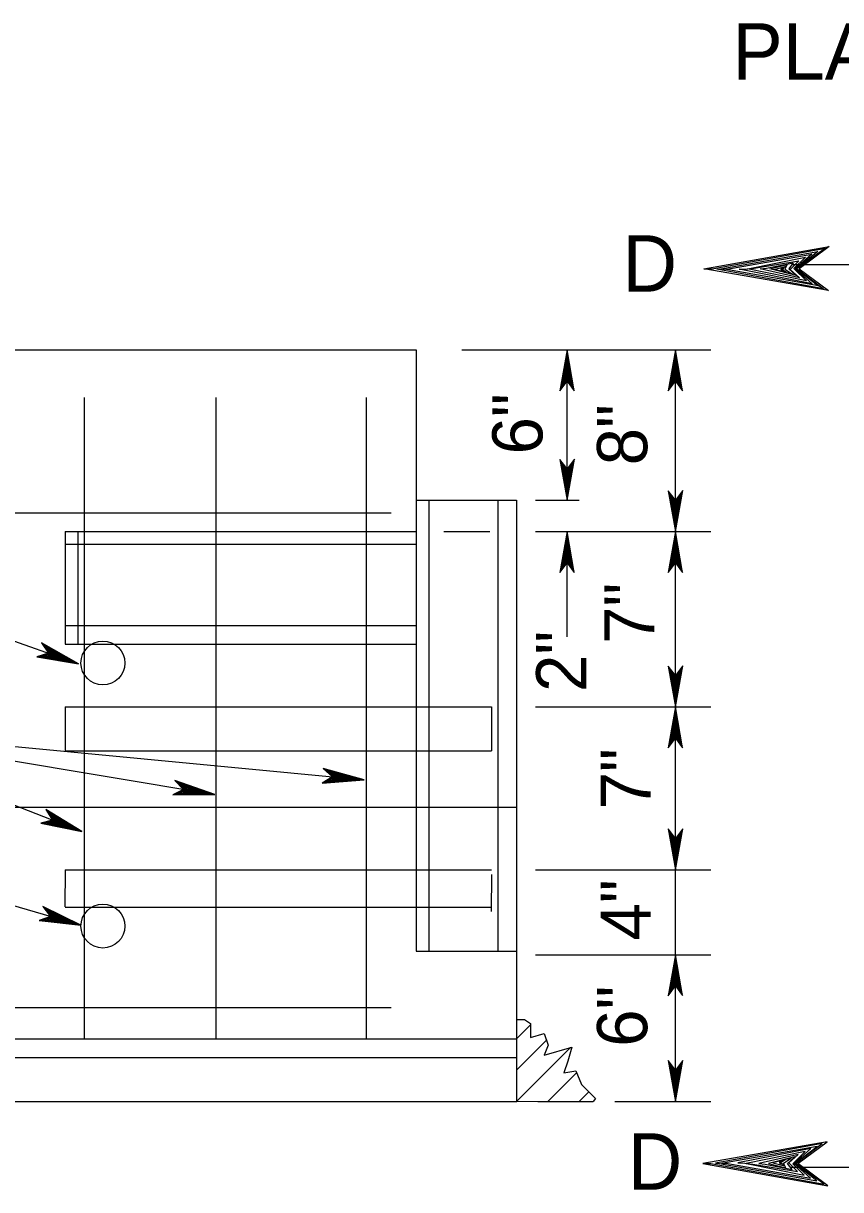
# Model space of a CAD drawing. Extents: x 499883 to 500983, y 499104 to 499764.
# Drawn here: x 500056.1 to 500121.3, y 499574.2 to 499667.2 of the extents above; entities that cross this region are included whole.
import ezdxf

# ---------------------------------------------------------------- set-up
doc = ezdxf.new("R2010")
doc.units = 0
for name, color, linetype in [('24', 7, 'Continuous'), ('5', 7, 'Continuous'), ('60', 7, 'Continuous')]:
    doc.layers.add(name, color=color, linetype=linetype)

msp = doc.modelspace()

# ---------------------------------------------------------------- linework, layer by layer
at = {"layer": '24'}
for points in [[(500099.463, 499641.156), (500098.884, 499637.882), (500099.463, 499638.665), (500100.033, 499637.899), (500099.463, 499641.156), (500099.469, 499640.939), (500098.927, 499637.974), (500099.47, 499638.726), (500099.988, 499638.032), (500099.479, 499640.822), (500099.463, 499640.713), (500099.011, 499638.173), (500099.47, 499638.743), (500099.914, 499638.157), (500099.462, 499640.663), (500099.479, 499640.554), (500099.078, 499638.334), (500099.462, 499638.766), (500099.862, 499638.325), (500099.479, 499640.238), (500099.479, 499640.053), (500099.161, 499638.499), (500099.454, 499638.801), (500099.779, 499638.475), (500099.463, 499640.02), (500099.453, 499639.845), (500099.253, 499638.677), (500099.479, 499638.901), (500099.704, 499638.658), (500099.463, 499639.685), (500099.446, 499639.52), (500099.312, 499638.818), (500099.47, 499638.934), (500099.645, 499638.742), (500099.462, 499639.435), (500099.354, 499638.977), (500099.479, 499639.043), (500099.605, 499638.842), (500099.479, 499639.319), (500099.404, 499639.019), (500099.503, 499639.145), (500099.562, 499639), (500099.47, 499639.144), (500099.454, 499639.069)], [(500108.099, 499641.156), (500107.52, 499637.882), (500108.099, 499638.665), (500108.669, 499637.899), (500108.099, 499641.156), (500108.105, 499640.939), (500107.563, 499637.974), (500108.106, 499638.726), (500108.624, 499638.032), (500108.115, 499640.822), (500108.099, 499640.713), (500107.647, 499638.173), (500108.106, 499638.743), (500108.55, 499638.157), (500108.099, 499640.663), (500108.115, 499640.554), (500107.714, 499638.334), (500108.099, 499638.766), (500108.498, 499638.325), (500108.116, 499640.238), (500108.115, 499640.053), (500107.797, 499638.499), (500108.09, 499638.801), (500108.415, 499638.475), (500108.099, 499640.02), (500108.089, 499639.845), (500107.889, 499638.677), (500108.116, 499638.901), (500108.34, 499638.658), (500108.099, 499639.685), (500108.082, 499639.52), (500107.948, 499638.818), (500108.106, 499638.934), (500108.281, 499638.742), (500108.099, 499639.435), (500107.99, 499638.977), (500108.115, 499639.043), (500108.241, 499638.842), (500108.116, 499639.319), (500108.04, 499639.019), (500108.139, 499639.145), (500108.198, 499639), (500108.106, 499639.144), (500108.09, 499639.069)], [(500099.463, 499629.166), (500100.042, 499632.44), (500099.463, 499631.658), (500098.893, 499632.423), (500099.463, 499629.166), (500099.457, 499629.383), (500099.999, 499632.348), (500099.456, 499631.597), (500098.938, 499632.291), (500099.447, 499629.5), (500099.463, 499629.61), (500099.914, 499632.149), (500099.456, 499631.58), (500099.012, 499632.166), (500099.463, 499629.66), (500099.447, 499629.768), (500099.848, 499631.988), (500099.463, 499631.557), (500099.064, 499631.998), (500099.446, 499630.084), (500099.447, 499630.269), (500099.765, 499631.824), (500099.472, 499631.521), (500099.147, 499631.847), (500099.463, 499630.302), (500099.473, 499630.477), (500099.673, 499631.646), (500099.446, 499631.421), (500099.222, 499631.665), (500099.463, 499630.638), (500099.479, 499630.803), (500099.614, 499631.504), (500099.456, 499631.389), (500099.281, 499631.58), (500099.463, 499630.888), (500099.572, 499631.346), (500099.447, 499631.28), (500099.321, 499631.48), (500099.446, 499631.003), (500099.521, 499631.304), (500099.423, 499631.178), (500099.364, 499631.322), (500099.456, 499631.179), (500099.472, 499631.254)], [(500108.099, 499626.667), (500108.678, 499629.941), (500108.099, 499629.159), (500107.529, 499629.925), (500108.099, 499626.667), (500108.093, 499626.885), (500108.635, 499629.85), (500108.092, 499629.098), (500107.574, 499629.792), (500108.083, 499627.002), (500108.099, 499627.111), (500108.551, 499629.651), (500108.092, 499629.081), (500107.648, 499629.667), (500108.099, 499627.161), (500108.083, 499627.27), (500108.484, 499629.49), (500108.099, 499629.058), (500107.7, 499629.499), (500108.082, 499627.586), (500108.083, 499627.771), (500108.401, 499629.325), (500108.109, 499629.023), (500107.783, 499629.349), (500108.099, 499627.804), (500108.109, 499627.979), (500108.309, 499629.147), (500108.082, 499628.923), (500107.859, 499629.166), (500108.099, 499628.139), (500108.116, 499628.304), (500108.25, 499629.006), (500108.092, 499628.89), (500107.917, 499629.082), (500108.099, 499628.39), (500108.208, 499628.847), (500108.083, 499628.781), (500107.957, 499628.982), (500108.082, 499628.505), (500108.158, 499628.805), (500108.059, 499628.679), (500108, 499628.824), (500108.092, 499628.68), (500108.109, 499628.755)], [(500099.463, 499626.667), (500098.884, 499623.394), (500099.463, 499624.176), (500100.033, 499623.41), (500099.463, 499626.667), (500099.469, 499626.45), (500098.927, 499623.485), (500099.47, 499624.237), (500099.988, 499623.543), (500099.479, 499626.333), (500099.463, 499626.224), (500099.011, 499623.684), (500099.47, 499624.254), (500099.914, 499623.668), (500099.462, 499626.174), (500099.479, 499626.065), (500099.078, 499623.845), (500099.462, 499624.277), (500099.862, 499623.836), (500099.479, 499625.749), (500099.479, 499625.564), (500099.161, 499624.01), (500099.454, 499624.312), (500099.779, 499623.986), (500099.463, 499625.531), (500099.453, 499625.356), (500099.253, 499624.188), (500099.479, 499624.412), (500099.704, 499624.169), (500099.463, 499625.196), (500099.446, 499625.031), (500099.312, 499624.329), (500099.47, 499624.445), (500099.645, 499624.253), (500099.462, 499624.945), (500099.354, 499624.488), (500099.479, 499624.554), (500099.605, 499624.353), (500099.479, 499624.83), (500099.404, 499624.53), (500099.503, 499624.656), (500099.562, 499624.511), (500099.47, 499624.655), (500099.454, 499624.58)], [(500108.099, 499626.667), (500107.52, 499623.394), (500108.099, 499624.176), (500108.669, 499623.41), (500108.099, 499626.667), (500108.105, 499626.45), (500107.563, 499623.485), (500108.106, 499624.237), (500108.624, 499623.543), (500108.115, 499626.333), (500108.099, 499626.224), (500107.647, 499623.684), (500108.106, 499624.254), (500108.55, 499623.668), (500108.099, 499626.174), (500108.115, 499626.065), (500107.714, 499623.845), (500108.099, 499624.277), (500108.498, 499623.836), (500108.116, 499625.749), (500108.115, 499625.564), (500107.797, 499624.01), (500108.09, 499624.312), (500108.415, 499623.986), (500108.099, 499625.531), (500108.089, 499625.356), (500107.889, 499624.188), (500108.116, 499624.412), (500108.34, 499624.169), (500108.099, 499625.196), (500108.082, 499625.031), (500107.948, 499624.329), (500108.106, 499624.445), (500108.281, 499624.253), (500108.099, 499624.945), (500107.99, 499624.488), (500108.115, 499624.554), (500108.241, 499624.353), (500108.116, 499624.83), (500108.04, 499624.53), (500108.139, 499624.656), (500108.198, 499624.511), (500108.106, 499624.655), (500108.09, 499624.58)], [(500108.099, 499612.678), (500108.678, 499615.952), (500108.099, 499615.17), (500107.529, 499615.935), (500108.099, 499612.678), (500108.093, 499612.896), (500108.635, 499615.86), (500108.092, 499615.109), (500107.574, 499615.803), (500108.083, 499613.013), (500108.099, 499613.122), (500108.551, 499615.662), (500108.092, 499615.092), (500107.648, 499615.678), (500108.099, 499613.172), (500108.083, 499613.28), (500108.484, 499615.5), (500108.099, 499615.069), (500107.7, 499615.51), (500108.082, 499613.597), (500108.083, 499613.781), (500108.401, 499615.336), (500108.109, 499615.034), (500107.783, 499615.359), (500108.099, 499613.814), (500108.109, 499613.989), (500108.309, 499615.158), (500108.082, 499614.933), (500107.859, 499615.177), (500108.099, 499614.15), (500108.116, 499614.315), (500108.25, 499615.017), (500108.092, 499614.901), (500107.917, 499615.092), (500108.099, 499614.4), (500108.208, 499614.858), (500108.083, 499614.792), (500107.957, 499614.993), (500108.082, 499614.516), (500108.158, 499614.816), (500108.059, 499614.69), (500108, 499614.834), (500108.092, 499614.691), (500108.109, 499614.766)], [(500108.099, 499612.678), (500107.52, 499609.404), (500108.099, 499610.187), (500108.669, 499609.421), (500108.099, 499612.678), (500108.105, 499612.461), (500107.563, 499609.496), (500108.106, 499610.248), (500108.624, 499609.553), (500108.115, 499612.343), (500108.099, 499612.234), (500107.647, 499609.695), (500108.106, 499610.264), (500108.55, 499609.679), (500108.099, 499612.185), (500108.115, 499612.076), (500107.714, 499609.856), (500108.099, 499610.288), (500108.498, 499609.847), (500108.116, 499611.76), (500108.115, 499611.575), (500107.797, 499610.02), (500108.09, 499610.323), (500108.415, 499609.997), (500108.099, 499611.542), (500108.089, 499611.367), (500107.889, 499610.198), (500108.116, 499610.423), (500108.34, 499610.179), (500108.099, 499611.207), (500108.082, 499611.042), (500107.948, 499610.339), (500108.106, 499610.455), (500108.281, 499610.264), (500108.099, 499610.956), (500107.99, 499610.498), (500108.115, 499610.564), (500108.241, 499610.364), (500108.116, 499610.841), (500108.04, 499610.54), (500108.139, 499610.666), (500108.198, 499610.522), (500108.106, 499610.666), (500108.09, 499610.59)], [(500108.099, 499599.688), (500108.678, 499602.962), (500108.099, 499602.18), (500107.529, 499602.945), (500108.099, 499599.688), (500108.093, 499599.906), (500108.635, 499602.871), (500108.092, 499602.119), (500107.574, 499602.813), (500108.083, 499600.023), (500108.099, 499600.132), (500108.551, 499602.672), (500108.092, 499602.102), (500107.648, 499602.688), (500108.099, 499600.182), (500108.083, 499600.291), (500108.484, 499602.511), (500108.099, 499602.079), (500107.7, 499602.52), (500108.082, 499600.607), (500108.083, 499600.792), (500108.401, 499602.346), (500108.109, 499602.044), (500107.783, 499602.37), (500108.099, 499600.825), (500108.109, 499601), (500108.309, 499602.168), (500108.082, 499601.943), (500107.859, 499602.187), (500108.099, 499601.16), (500108.116, 499601.325), (500108.25, 499602.027), (500108.092, 499601.911), (500107.917, 499602.103), (500108.099, 499601.41), (500108.208, 499601.868), (500108.083, 499601.802), (500107.957, 499602.003), (500108.082, 499601.526), (500108.158, 499601.826), (500108.059, 499601.7), (500108, 499601.845), (500108.092, 499601.701), (500108.109, 499601.776)], [(500108.099, 499592.909), (500107.52, 499589.635), (500108.099, 499590.417), (500108.669, 499589.652), (500108.099, 499592.909), (500108.105, 499592.691), (500107.563, 499589.727), (500108.106, 499590.478), (500108.624, 499589.784), (500108.115, 499592.574), (500108.099, 499592.465), (500107.647, 499589.925), (500108.106, 499590.495), (500108.55, 499589.909), (500108.099, 499592.415), (500108.115, 499592.307), (500107.714, 499590.086), (500108.099, 499590.518), (500108.498, 499590.077), (500108.116, 499591.99), (500108.115, 499591.806), (500107.797, 499590.251), (500108.09, 499590.553), (500108.415, 499590.228), (500108.099, 499591.772), (500108.089, 499591.598), (500107.889, 499590.429), (500108.116, 499590.654), (500108.34, 499590.41), (500108.099, 499591.437), (500108.082, 499591.272), (500107.948, 499590.57), (500108.106, 499590.686), (500108.281, 499590.495), (500108.099, 499591.187), (500107.99, 499590.729), (500108.115, 499590.795), (500108.241, 499590.594), (500108.116, 499591.071), (500108.04, 499590.771), (500108.139, 499590.897), (500108.198, 499590.752), (500108.106, 499590.896), (500108.09, 499590.821)], [(500108.099, 499581.202), (500108.678, 499584.476), (500108.099, 499583.694), (500107.529, 499584.459), (500108.099, 499581.202), (500108.093, 499581.419), (500108.635, 499584.384), (500108.092, 499583.633), (500107.574, 499584.327), (500108.083, 499581.537), (500108.099, 499581.646), (500108.551, 499584.186), (500108.092, 499583.616), (500107.648, 499584.202), (500108.099, 499581.696), (500108.083, 499581.805), (500108.484, 499584.024), (500108.099, 499583.593), (500107.7, 499584.034), (500108.082, 499582.121), (500108.083, 499582.305), (500108.401, 499583.86), (500108.109, 499583.558), (500107.783, 499583.883), (500108.099, 499582.338), (500108.109, 499582.513), (500108.309, 499583.682), (500108.082, 499583.457), (500107.859, 499583.701), (500108.099, 499582.674), (500108.116, 499582.839), (500108.25, 499583.541), (500108.092, 499583.425), (500107.917, 499583.616), (500108.099, 499582.924), (500108.208, 499583.382), (500108.083, 499583.316), (500107.957, 499583.517), (500108.082, 499583.04), (500108.158, 499583.34), (500108.059, 499583.214), (500108, 499583.358), (500108.092, 499583.215), (500108.109, 499583.29)]]:
    msp.add_lwpolyline(points, dxfattribs=at)
at = {"layer": '5'}
for p, q in [((500127.405, 499647.934), (500117.412, 499647.934)), ((500014.216, 499641.156), (500087.439, 499641.156)), ((500087.439, 499641.156), (500087.439, 499629.166)), ((500091.082, 499641.156), (500110.933, 499641.156)), ((500099.463, 499629.166), (500099.463, 499641.156)), ((500108.099, 499626.667), (500108.099, 499641.156)), ((500060.959, 499637.369), (500060.959, 499586.199)), ((500071.451, 499637.369), (500071.451, 499586.199)), ((500083.442, 499637.369), (500083.442, 499586.199)), ((500087.439, 499629.166), (500095.433, 499629.166)), ((500087.439, 499629.166), (500087.439, 499593.193)), ((500088.438, 499629.166), (500088.438, 499593.193)), ((500093.934, 499629.166), (500093.934, 499593.193)), ((500095.433, 499629.166), (500095.433, 499581.202)), ((500096.945, 499629.166), (500100.429, 499629.166)), ((500014.216, 499628.167), (500085.44, 499628.167)), ((500059.46, 499626.667), (500087.439, 499626.667)), ((500059.46, 499626.667), (500059.46, 499617.675)), ((500060.459, 499626.667), (500060.459, 499617.675)), ((500089.64, 499626.667), (500093.292, 499626.667)), ((500096.945, 499626.667), (500110.933, 499626.667)), ((500099.463, 499618.265), (500099.463, 499626.667)), ((500108.099, 499612.678), (500108.099, 499626.667)), ((500059.46, 499625.668), (500087.439, 499625.668)), ((500046.578, 499621.022), (500060.517, 499616.121)), ((500059.46, 499619.173), (500087.439, 499619.173)), ((500059.46, 499617.675), (500087.439, 499617.675)), ((500059.46, 499612.678), (500093.434, 499612.678)), ((500059.46, 499612.678), (500059.46, 499609.181)), ((500093.434, 499612.678), (500093.434, 499609.181)), ((500096.945, 499612.678), (500110.933, 499612.678)), ((500108.099, 499599.688), (500108.099, 499612.678)), ((500039.465, 499611.026), (500083.279, 499606.856)), ((500039.465, 499611.026), (500071.389, 499605.679)), ((500039.465, 499611.026), (500060.794, 499602.736)), ((500059.46, 499609.181), (500093.434, 499609.181)), ((500014.216, 499604.685), (500095.433, 499604.685)), ((500039.85, 499601.319), (500060.709, 499595.264)), ((500059.46, 499599.688), (500059.428, 499596.737)), ((500059.46, 499599.688), (500093.434, 499599.688)), ((500096.945, 499599.688), (500110.933, 499599.688)), ((500108.099, 499592.909), (500108.099, 499599.688)), ((500093.43, 499599.315), (500093.398, 499596.364)), ((500059.46, 499596.69), (500093.434, 499596.69)), ((500087.439, 499593.193), (500095.433, 499593.193)), ((500096.945, 499592.909), (500110.933, 499592.909)), ((500108.099, 499581.202), (500108.099, 499592.909)), ((500014.216, 499588.697), (500085.44, 499588.697)), ((500095.433, 499586.199), (500096.539, 499587.305)), ((500014.216, 499586.199), (500095.433, 499586.199)), ((500095.433, 499583.7), (500097.82, 499586.087)), ((500014.216, 499584.699), (500095.433, 499584.699)), ((500095.433, 499581.202), (500099.731, 499585.5)), ((500097.931, 499581.202), (500100.219, 499583.49)), ((500100.429, 499581.202), (500101.198, 499581.971)), ((500014.216, 499581.202), (500095.433, 499581.202)), ((500097.137, 499581.202), (500101.537, 499581.202)), ((500103.262, 499581.202), (500110.933, 499581.202)), ((500127.305, 499575.943), (500117.312, 499575.943))]:
    msp.add_line(p, q, dxfattribs=at)
for points in [[(500110.372, 499647.632), (500120.344, 499649.395), (500117.962, 499647.632), (500120.292, 499645.897), (500110.372, 499647.632), (500111.035, 499647.614), (500120.064, 499649.264), (500117.775, 499647.61), (500119.89, 499646.034), (500111.392, 499647.583), (500111.724, 499647.632), (500119.459, 499649.007), (500117.724, 499647.612), (500119.509, 499646.258), (500111.876, 499647.632), (500112.207, 499647.583), (500118.969, 499648.803), (500117.654, 499647.632), (500118.996, 499646.416), (500113.17, 499647.582), (500113.733, 499647.583), (500118.467, 499648.552), (500117.546, 499647.66), (500118.538, 499646.669), (500113.833, 499647.632), (500114.366, 499647.663), (500117.926, 499648.272), (500117.241, 499647.581), (500117.983, 499646.899), (500114.855, 499647.632), (500115.357, 499647.683), (500117.495, 499648.091), (500117.143, 499647.61), (500117.725, 499647.078), (500115.618, 499647.633), (500117.012, 499647.963), (500116.811, 499647.583), (500117.422, 499647.2), (500115.968, 499647.581), (500116.883, 499647.811), (500116.5, 499647.509), (500116.94, 499647.329), (500116.502, 499647.61), (500116.732, 499647.66)], [(500060.517, 499616.121), (500057.576, 499617.778), (500058.13, 499616.96), (500057.205, 499616.672), (500060.517, 499616.121), (500060.306, 499616.188), (500057.649, 499617.706), (500058.186, 499616.933), (500057.347, 499616.671), (500060.19, 499616.218), (500060.092, 499616.27), (500057.811, 499617.558), (500058.203, 499616.927), (500057.492, 499616.699), (500060.044, 499616.287), (500059.934, 499616.309), (500057.943, 499617.439), (500058.227, 499616.926), (500057.67, 499616.692), (500059.631, 499616.414), (500059.454, 499616.477), (500058.073, 499617.305), (500058.264, 499616.923), (500057.842, 499616.721), (500059.429, 499616.503), (500059.265, 499616.572), (500058.212, 499617.158), (500058.351, 499616.864), (500058.042, 499616.732), (500059.107, 499616.616), (500058.954, 499616.688), (500058.328, 499617.053), (500058.385, 499616.863), (500058.143, 499616.76), (500058.867, 499616.701), (500058.466, 499616.959), (500058.487, 499616.817), (500058.252, 499616.765), (500058.751, 499616.724), (500058.489, 499616.897), (500058.576, 499616.76), (500058.418, 499616.752), (500058.587, 499616.792), (500058.52, 499616.833)], [(500083.279, 499606.856), (500080.026, 499607.756), (500080.761, 499607.096), (500079.933, 499606.594), (500083.279, 499606.856), (500083.058, 499606.871), (500080.115, 499607.704), (500080.822, 499607.083), (500080.071, 499606.626), (500082.939, 499606.872), (500082.83, 499606.899), (500080.307, 499607.599), (500080.839, 499607.082), (500080.204, 499606.689), (500082.78, 499606.904), (500082.669, 499606.898), (500080.463, 499607.516), (500080.863, 499607.086), (500080.379, 499606.725), (500082.349, 499606.928), (500082.162, 499606.946), (500080.622, 499607.417), (500080.899, 499607.092), (500080.539, 499606.795), (500082.131, 499606.965), (500081.955, 499606.993), (500080.793, 499607.307), (500080.998, 499607.057), (500080.731, 499606.853), (500081.792, 499606.998), (500081.627, 499607.03), (500080.93, 499607.234), (500081.032, 499607.063), (500080.822, 499606.905), (500081.538, 499607.022), (500081.086, 499607.176), (500081.141, 499607.043), (500080.926, 499606.936), (500081.42, 499607.016), (500081.124, 499607.121), (500081.242, 499607.009), (500081.09, 499606.963), (500081.245, 499607.043), (500081.17, 499607.067)], [(500071.389, 499605.679), (500068.208, 499606.808), (500068.894, 499606.097), (500068.032, 499605.655), (500071.389, 499605.679), (500071.17, 499605.709), (500068.292, 499606.75), (500068.954, 499606.08), (500068.172, 499605.678), (500071.051, 499605.719), (500070.944, 499605.753), (500068.477, 499606.631), (500068.971, 499606.077), (500068.31, 499605.73), (500070.895, 499605.762), (500070.783, 499605.764), (500068.627, 499606.537), (500068.995, 499606.08), (500068.487, 499605.754), (500070.466, 499605.817), (500070.281, 499605.848), (500068.778, 499606.427), (500069.032, 499606.083), (500068.651, 499605.812), (500070.251, 499605.87), (500070.078, 499605.909), (500068.941, 499606.306), (500069.128, 499606.041), (500068.847, 499605.857), (500069.915, 499605.926), (500069.753, 499605.97), (500069.073, 499606.222), (500069.162, 499606.045), (500068.941, 499605.902), (500069.664, 499605.968), (500069.225, 499606.154), (500069.269, 499606.017), (500069.048, 499605.925), (500069.546, 499605.971), (500069.258, 499606.096), (500069.368, 499605.976), (500069.213, 499605.941), (500069.373, 499606.01), (500069.3, 499606.038)], [(500060.794, 499602.736), (500057.909, 499604.488), (500058.436, 499603.652), (500057.502, 499603.395), (500060.794, 499602.736), (500060.586, 499602.81), (500057.98, 499604.414), (500058.491, 499603.624), (500057.644, 499603.389), (500060.471, 499602.844), (500060.374, 499602.899), (500058.137, 499604.26), (500058.507, 499603.618), (500057.789, 499603.412), (500060.327, 499602.918), (500060.218, 499602.942), (500058.265, 499604.138), (500058.532, 499603.616), (500057.968, 499603.4), (500059.918, 499603.058), (500059.744, 499603.126), (500058.39, 499604), (500058.568, 499603.611), (500058.141, 499603.423), (500059.719, 499603.154), (500059.557, 499603.228), (500058.524, 499603.847), (500058.653, 499603.55), (500058.341, 499603.427), (500059.401, 499603.277), (500059.251, 499603.354), (500058.637, 499603.739), (500058.688, 499603.547), (500058.442, 499603.452), (500059.164, 499603.37), (500058.771, 499603.641), (500058.787, 499603.498), (500058.552, 499603.453), (500059.049, 499603.396), (500058.792, 499603.578), (500058.875, 499603.438), (500058.717, 499603.435), (500058.887, 499603.469), (500058.822, 499603.513)], [(500060.709, 499595.264), (500057.681, 499596.754), (500058.279, 499595.969), (500057.372, 499595.63), (500060.709, 499595.264), (500060.495, 499595.319), (500057.758, 499596.687), (500058.337, 499595.945), (500057.514, 499595.636), (500060.378, 499595.343), (500060.276, 499595.389), (500057.928, 499596.548), (500058.354, 499595.94), (500057.657, 499595.673), (500060.227, 499595.403), (500060.117, 499595.418), (500058.066, 499596.437), (500058.378, 499595.94), (500057.835, 499595.676), (500059.808, 499595.507), (500059.629, 499595.56), (500058.203, 499596.311), (500058.415, 499595.939), (500058.005, 499595.714), (500059.601, 499595.585), (500059.433, 499595.644), (500058.35, 499596.171), (500058.505, 499595.886), (500058.204, 499595.736), (500059.274, 499595.68), (500059.118, 499595.743), (500058.472, 499596.073), (500058.54, 499595.886), (500058.304, 499595.77), (500059.03, 499595.751), (500058.615, 499595.987), (500058.643, 499595.846), (500058.412, 499595.78), (500058.913, 499595.767), (500058.641, 499595.926), (500058.736, 499595.793), (500058.579, 499595.777), (500058.745, 499595.826), (500058.676, 499595.864)], [(500095.44, 499587.73), (500096.068, 499587.73), (500096.539, 499587.416), (500096.539, 499586.316), (500097.639, 499586.63), (500097.953, 499585.688), (500097.639, 499584.902), (500099.838, 499585.53), (500099.524, 499584.431), (500099.21, 499583.488), (500100.152, 499583.646), (500100.623, 499582.546), (500101.723, 499581.447), (500101.537, 499581.201), (500095.45, 499581.182)], [(500110.272, 499576.244), (500120.244, 499574.482), (500117.861, 499576.244), (500120.192, 499577.979), (500110.272, 499576.244), (500110.934, 499576.263), (500119.964, 499574.612), (500117.675, 499576.266), (500119.789, 499577.843), (500111.292, 499576.293), (500111.624, 499576.244), (500119.359, 499574.87), (500117.623, 499576.265), (500119.408, 499577.618), (500111.775, 499576.244), (500112.107, 499576.293), (500118.869, 499575.073), (500117.554, 499576.244), (500118.895, 499577.46), (500113.07, 499576.295), (500113.632, 499576.294), (500118.367, 499575.325), (500117.446, 499576.216), (500118.438, 499577.208), (500113.733, 499576.244), (500114.265, 499576.213), (500117.826, 499575.604), (500117.141, 499576.295), (500117.883, 499576.978), (500114.755, 499576.244), (500115.257, 499576.194), (500117.394, 499575.785), (500117.042, 499576.266), (500117.625, 499576.798), (500115.517, 499576.243), (500116.911, 499575.913), (500116.71, 499576.294), (500117.322, 499576.676), (500115.868, 499576.295), (500116.783, 499576.065), (500116.4, 499576.367), (500116.839, 499576.547), (500116.401, 499576.266), (500116.631, 499576.216)]]:
    msp.add_lwpolyline(points, dxfattribs=at)
at = {"layer": '60'}
for centre in [(500062.458, 499616.176), (500062.458, 499595.192)]:
    msp.add_circle(centre, 1.749, dxfattribs=at)

# ---------------------------------------------------------------- texts
at = {"layer": '5'}
for s, p in [('PLAN', (500112.64, 499662.705)), ('D', (500103.884, 499645.801)), ('D', (500104.297, 499574.167))]:
    msp.add_text(s, height=4.5, dxfattribs=at).set_placement(p)
for s, p in [('6"', (500097.498, 499632.818)), ('8"', (500105.849, 499631.948)), ('7"', (500106.419, 499617.709)), ('2"', (500100.993, 499613.874)), ('7"', (500106.134, 499604.504)), ('4"', (500106.134, 499594.048)), ('6"', (500105.849, 499585.569))]:
    msp.add_text(s, height=4, rotation=90, dxfattribs=at).set_placement(p)

doc.saveas('drawing.dxf')
